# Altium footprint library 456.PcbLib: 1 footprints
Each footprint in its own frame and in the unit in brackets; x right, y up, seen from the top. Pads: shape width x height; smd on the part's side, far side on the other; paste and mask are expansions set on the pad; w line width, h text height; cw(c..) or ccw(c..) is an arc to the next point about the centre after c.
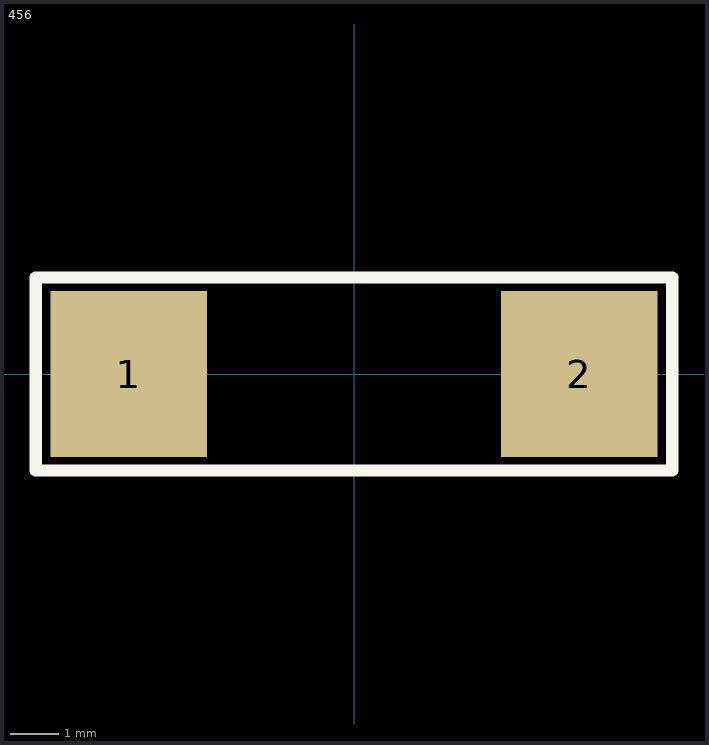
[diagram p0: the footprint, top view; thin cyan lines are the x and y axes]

## 456 [mm] "LITTELFUSE 456 SERIES FUSE"
height 3.12
pads (2):
  rect 3.25x3.44 smd: 1(-4.675,0) 2(4.675,0)
Top Overlay:
  lines w0.254: -6.6,-2 -6.6,2 6.6,2 6.6,-2 -6.6,-2
M5 Assembly Top:
  text ".Designator" at -0.1,-0.1 h1.02
3D body: height 3.12, standoff 0, extent -6.6,-2 6.6,2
